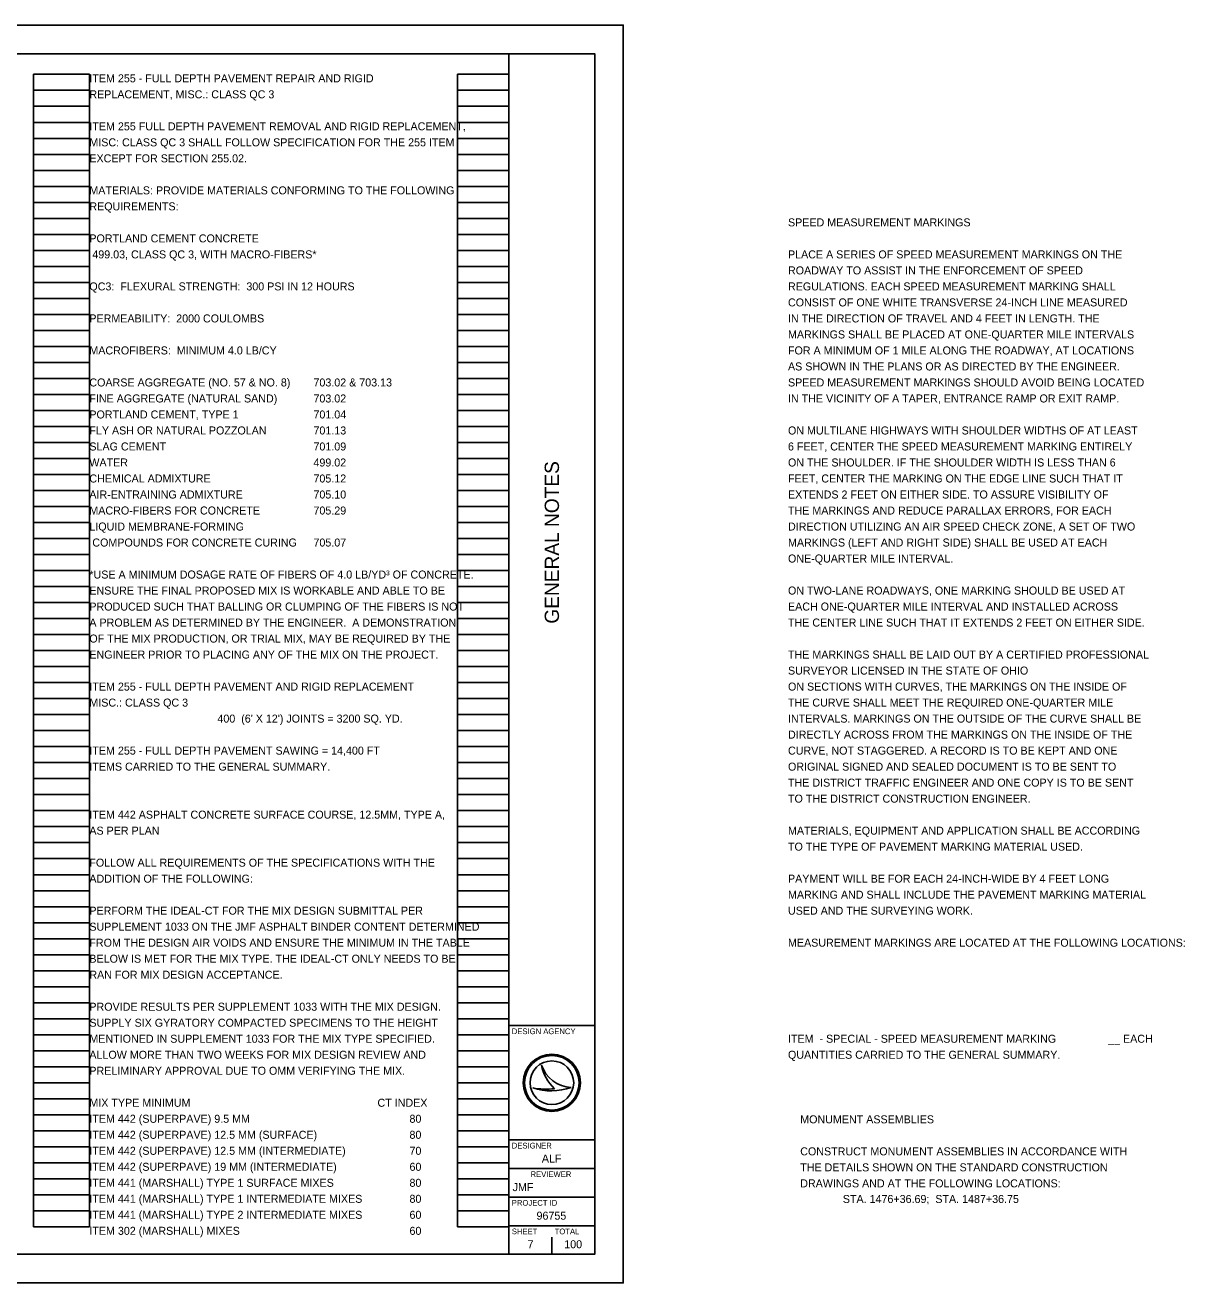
# Model space of a CAD drawing. Extents: x 0 to 43.8, y 0 to 22.
# Drawn here: x 23.54 to 43.82, y 0 to 22 of the extents above; entities that cross this region are included whole.
import ezdxf

# ---------------------------------------------------------------- set-up
doc = ezdxf.new("R2010")
doc.units = 0
for name, color, linetype in [('Default', 7, 'Continuous'), ('SH_Border', 7, 'Continuous'), ('SH_Cut_Line', 7, 'Continuous'), ('SH_Data', 7, 'Continuous'), ('SH_Text', 7, 'Continuous')]:
    doc.layers.add(name, color=color, linetype=linetype)

msp = doc.modelspace()

# ---------------------------------------------------------------- linework, layer by layer
at = {"layer": 'SH_Border'}
for p, q in [((32, 0.5), (32, 21.5)), ((32, 4.5), (33.5, 4.5)), ((32, 2.5), (33.5, 2.5)), ((32, 2), (33.5, 2)), ((32, 1.5), (33.5, 1.5)), ((32, 1), (33.5, 1))]:
    msp.add_line(p, q, dxfattribs=at)
msp.add_lwpolyline([(1.5, 21.5), (33.5, 21.5), (33.5, 0.5), (1.5, 0.5)], close=True, dxfattribs=at)
at = {"layer": 'SH_Cut_Line'}
msp.add_lwpolyline([(0, 0), (34, 0), (34, 22), (0, 22)], close=True, dxfattribs=at)
at = {"layer": 'SH_Data'}
for p, q in [((23.68, 0.98), (23.68, 21.14)), ((23.68, 21.14), (24.66, 21.14)), ((24.66, 0.98), (24.66, 21.14)), ((31.1, 0.98), (31.1, 21.14)), ((31.1, 21.14), (32, 21.14)), ((32, 0.98), (32, 21.14)), ((23.68, 20.86), (24.66, 20.86)), ((31.1, 20.86), (32, 20.86)), ((23.68, 20.58), (24.66, 20.58)), ((31.1, 20.58), (32, 20.58)), ((23.68, 20.3), (24.66, 20.3)), ((31.1, 20.3), (32, 20.3)), ((23.68, 20.02), (24.66, 20.02)), ((31.1, 20.02), (32, 20.02)), ((23.68, 19.74), (24.66, 19.74)), ((31.1, 19.74), (32, 19.74)), ((23.68, 19.46), (24.66, 19.46)), ((31.1, 19.46), (32, 19.46)), ((23.68, 19.18), (24.66, 19.18)), ((31.1, 19.18), (32, 19.18)), ((23.68, 18.9), (24.66, 18.9)), ((31.1, 18.9), (32, 18.9)), ((23.68, 18.62), (24.66, 18.62)), ((31.1, 18.62), (32, 18.62)), ((23.68, 18.34), (24.66, 18.34)), ((31.1, 18.34), (32, 18.34)), ((23.68, 18.06), (24.66, 18.06)), ((31.1, 18.06), (32, 18.06)), ((23.68, 17.78), (24.66, 17.78)), ((31.1, 17.78), (32, 17.78)), ((23.68, 17.5), (24.66, 17.5)), ((31.1, 17.5), (32, 17.5)), ((23.68, 17.22), (24.66, 17.22)), ((31.1, 17.22), (32, 17.22)), ((23.68, 16.94), (24.66, 16.94)), ((31.1, 16.94), (32, 16.94)), ((23.68, 16.66), (24.66, 16.66)), ((31.1, 16.66), (32, 16.66)), ((23.68, 16.38), (24.66, 16.38)), ((31.1, 16.38), (32, 16.38)), ((23.68, 16.1), (24.66, 16.1)), ((31.1, 16.1), (32, 16.1)), ((23.68, 15.82), (24.66, 15.82)), ((31.1, 15.82), (32, 15.82)), ((23.68, 15.54), (24.66, 15.54)), ((31.1, 15.54), (32, 15.54)), ((23.68, 15.26), (24.66, 15.26)), ((31.1, 15.26), (32, 15.26)), ((23.68, 14.98), (24.66, 14.98)), ((31.1, 14.98), (32, 14.98)), ((23.68, 14.7), (24.66, 14.7)), ((31.1, 14.7), (32, 14.7)), ((23.68, 14.42), (24.66, 14.42)), ((31.1, 14.42), (32, 14.42)), ((23.68, 14.14), (24.66, 14.14)), ((31.1, 14.14), (32, 14.14)), ((23.68, 13.86), (24.66, 13.86)), ((31.1, 13.86), (32, 13.86)), ((23.68, 13.58), (24.66, 13.58)), ((31.1, 13.58), (32, 13.58)), ((23.68, 13.3), (24.66, 13.3)), ((31.1, 13.3), (32, 13.3)), ((23.68, 13.02), (24.66, 13.02)), ((31.1, 13.02), (32, 13.02)), ((23.68, 12.74), (24.66, 12.74)), ((31.1, 12.74), (32, 12.74)), ((23.68, 12.46), (24.66, 12.46)), ((31.1, 12.46), (32, 12.46)), ((23.68, 12.18), (24.66, 12.18)), ((31.1, 12.18), (32, 12.18)), ((23.68, 11.9), (24.66, 11.9)), ((31.1, 11.9), (32, 11.9)), ((23.68, 11.62), (24.66, 11.62)), ((31.1, 11.62), (32, 11.62)), ((23.68, 11.34), (24.66, 11.34)), ((31.1, 11.34), (32, 11.34)), ((23.68, 11.06), (24.66, 11.06)), ((31.1, 11.06), (32, 11.06)), ((23.68, 10.78), (24.66, 10.78)), ((31.1, 10.78), (32, 10.78)), ((23.68, 10.5), (24.66, 10.5)), ((31.1, 10.5), (32, 10.5)), ((23.68, 10.22), (24.66, 10.22)), ((31.1, 10.22), (32, 10.22)), ((23.68, 9.94), (24.66, 9.94)), ((31.1, 9.94), (32, 9.94)), ((23.68, 9.66), (24.66, 9.66)), ((31.1, 9.66), (32, 9.66)), ((23.68, 9.38), (24.66, 9.38)), ((31.1, 9.38), (32, 9.38)), ((23.68, 9.1), (24.66, 9.1)), ((31.1, 9.1), (32, 9.1)), ((23.68, 8.82), (24.66, 8.82)), ((31.1, 8.82), (32, 8.82)), ((23.68, 8.54), (24.66, 8.54)), ((31.1, 8.54), (32, 8.54)), ((23.68, 8.26), (24.66, 8.26)), ((31.1, 8.26), (32, 8.26)), ((23.68, 7.98), (24.66, 7.98)), ((31.1, 7.98), (32, 7.98)), ((23.68, 7.7), (24.66, 7.7)), ((31.1, 7.7), (32, 7.7)), ((23.68, 7.42), (24.66, 7.42)), ((31.1, 7.42), (32, 7.42)), ((23.68, 7.14), (24.66, 7.14)), ((31.1, 7.14), (32, 7.14)), ((23.68, 6.86), (24.66, 6.86)), ((31.1, 6.86), (32, 6.86)), ((23.68, 6.58), (24.66, 6.58)), ((31.1, 6.58), (32, 6.58)), ((23.68, 6.3), (24.66, 6.3)), ((31.1, 6.3), (32, 6.3)), ((23.68, 6.02), (24.66, 6.02)), ((31.1, 6.02), (32, 6.02)), ((23.68, 5.74), (24.66, 5.74)), ((31.1, 5.74), (32, 5.74)), ((23.68, 5.46), (24.66, 5.46)), ((31.1, 5.46), (32, 5.46)), ((23.68, 5.18), (24.66, 5.18)), ((31.1, 5.18), (32, 5.18)), ((23.68, 4.9), (24.66, 4.9)), ((31.1, 4.9), (32, 4.9)), ((23.68, 4.62), (24.66, 4.62)), ((31.1, 4.62), (32, 4.62)), ((23.68, 4.34), (24.66, 4.34)), ((31.1, 4.34), (32, 4.34)), ((23.68, 4.06), (24.66, 4.06)), ((31.1, 4.06), (32, 4.06)), ((23.68, 3.78), (24.66, 3.78)), ((31.1, 3.78), (32, 3.78)), ((32.567, 3.81), (32.567, 3.81)), ((23.68, 3.5), (24.66, 3.5)), ((31.1, 3.5), (32, 3.5)), ((32.417, 3.41), (32.417, 3.41)), ((32.75, 3.5), (32.75, 3.5)), ((33.087, 3.419), (33.087, 3.419)), ((23.68, 3.22), (24.66, 3.22)), ((31.1, 3.22), (32, 3.22)), ((23.68, 2.94), (24.66, 2.94)), ((31.1, 2.94), (32, 2.94)), ((23.68, 2.66), (24.66, 2.66)), ((31.1, 2.66), (32, 2.66)), ((23.68, 2.38), (24.66, 2.38)), ((31.1, 2.38), (32, 2.38)), ((23.68, 2.1), (24.66, 2.1)), ((31.1, 2.1), (32, 2.1)), ((23.68, 1.82), (24.66, 1.82)), ((31.1, 1.82), (32, 1.82)), ((23.68, 1.54), (24.66, 1.54)), ((31.1, 1.54), (32, 1.54)), ((23.68, 1.26), (24.66, 1.26)), ((31.1, 1.26), (32, 1.26)), ((23.68, 0.98), (24.66, 0.98)), ((31.1, 0.98), (32, 0.98)), ((32.375, 0.675), (32.375, 0.675)), ((32.75, 0.5), (32.75, 0.8))]:
    msp.add_line(p, q, dxfattribs=at)
for radius in [0.5, 0.477, 0.477, 0.382]:
    msp.add_circle((32.75, 3.5), radius, dxfattribs=at)
for centre, radius, start, end in [((33.116, 3.998), 0.58, 198.9257, 198.9319), ((33.347, 3.97), 0.796, 191.6379, 191.6421), ((33.116, 3.998), 0.58, 198.9319, 267.1657), ((33.347, 3.97), 0.796, 191.6421, 226.0947), ((32.739, 4.37), 1.013, 251.4576, 290.0832), ((32.648, 4.654), 1.266, 259.4964, 259.4995), ((32.739, 4.37), 1.013, 251.4527, 251.4576), ((32.648, 4.654), 1.266, 259.4995, 276.6672)]:
    msp.add_arc(centre, radius, start, end, dxfattribs=at)

# ---------------------------------------------------------------- texts
at = {"layer": 'Default'}
for s, p in [('ITEM 442 ASPHALT CONCRETE SURFACE COURSE, 12.5MM, TYPE A,', (24.66, 8.12)), ('AS PER PLAN', (24.66, 7.84)), ('FOLLOW ALL REQUIREMENTS OF THE SPECIFICATIONS WITH THE ', (24.66, 7.28)), ('ADDITION OF THE FOLLOWING:', (24.66, 7)), ('PERFORM THE IDEAL-CT FOR THE MIX DESIGN SUBMITTAL PER', (24.66, 6.44)), ('SUPPLEMENT 1033 ON THE JMF ASPHALT BINDER CONTENT DETERMINED', (24.66, 6.16)), ('FROM THE DESIGN AIR VOIDS AND ENSURE THE MINIMUM IN THE TABLE', (24.66, 5.88)), ('BELOW IS MET FOR THE MIX TYPE. THE IDEAL-CT ONLY NEEDS TO BE', (24.66, 5.6)), ('RAN FOR MIX DESIGN ACCEPTANCE.', (24.66, 5.32)), ('PROVIDE RESULTS PER SUPPLEMENT 1033 WITH THE MIX DESIGN.', (24.66, 4.76)), ('SUPPLY SIX GYRATORY COMPACTED SPECIMENS TO THE HEIGHT', (24.66, 4.48)), ('MENTIONED IN SUPPLEMENT 1033 FOR THE MIX TYPE SPECIFIED.', (24.66, 4.2)), ('ALLOW MORE THAN TWO WEEKS FOR MIX DESIGN REVIEW AND', (24.66, 3.92)), ('PRELIMINARY APPROVAL DUE TO OMM VERIFYING THE MIX. ', (24.66, 3.64)), ('MIX TYPE MINIMUM                                           ', (24.66, 3.08)), ('CT INDEX', (29.7, 3.08)), ('ITEM 442 (SUPERPAVE) 9.5 MM                              ', (24.66, 2.8)), ('80', (30.26, 2.8)), ('ITEM 442 (SUPERPAVE) 12.5 MM (SURFACE)             ', (24.66, 2.52)), ('80', (30.26, 2.52)), ('ITEM 442 (SUPERPAVE) 12.5 MM (INTERMEDIATE)     ', (24.66, 2.24)), ('70', (30.26, 2.24)), ('ITEM 442 (SUPERPAVE) 19 MM (INTERMEDIATE)        ', (24.66, 1.96)), ('60', (30.26, 1.96)), ('ITEM 441 (MARSHALL) TYPE 1 SURFACE MIXES           ', (24.66, 1.68)), ('80', (30.26, 1.68)), ('ITEM 441 (MARSHALL) TYPE 1 INTERMEDIATE MIXES     ', (24.66, 1.4)), ('80', (30.26, 1.4)), ('ITEM 441 (MARSHALL) TYPE 2 INTERMEDIATE MIXES     ', (24.66, 1.12)), ('60', (30.26, 1.12)), ('ITEM 302 (MARSHALL) MIXES                                      ', (24.66, 0.84)), ('60', (30.26, 0.84))]:
    msp.add_text(s, height=0.14, dxfattribs=at).set_placement(p)
at = {"layer": 'SH_Data'}
msp.add_text('GENERAL NOTES', height=0.25, rotation=90, dxfattribs=at).set_placement((32.875, 11.531))
for s, height, p in [('DESIGN AGENCY', 0.1, (32.05, 4.35)), ('DESIGNER', 0.1, (32.05, 2.35)), ('ALF', 0.14, (32.575, 2.105)), ('REVIEWER', 0.1, (32.378, 1.85)), ('JMF', 0.14, (32.064, 1.605)), ('PROJECT ID', 0.1, (32.05, 1.35)), ('96755', 0.14, (32.482, 1.105)), ('SHEET', 0.1, (32.05, 0.85)), ('TOTAL', 0.1, (32.8, 0.85)), ('7', 0.14, (32.325, 0.605)), ('100', 0.14, (32.967, 0.605))]:
    msp.add_text(s, height=height, dxfattribs=at).set_placement(p)
at = {"layer": 'SH_Text'}
for s, p in [('ITEM 255 - FULL DEPTH PAVEMENT REPAIR AND RIGID', (24.66, 21)), ('REPLACEMENT, MISC.: CLASS QC 3', (24.66, 20.72)), ('ITEM 255 FULL DEPTH PAVEMENT REMOVAL AND RIGID REPLACEMENT,', (24.66, 20.16)), ('MISC: CLASS QC 3 SHALL FOLLOW SPECIFICATION FOR THE 255 ITEM', (24.66, 19.88)), ('EXCEPT FOR SECTION 255.02.', (24.66, 19.6)), ('MATERIALS: PROVIDE MATERIALS CONFORMING TO THE FOLLOWING', (24.66, 19.04)), ('REQUIREMENTS:', (24.66, 18.76)), ('SPEED MEASUREMENT MARKINGS', (36.881, 18.48)), ('PORTLAND CEMENT CONCRETE', (24.66, 18.2)), (' 499.03, CLASS QC 3, WITH MACRO-FIBERS*', (24.66, 17.92)), ('PLACE A SERIES OF SPEED MEASUREMENT MARKINGS ON THE', (36.881, 17.92)), ('ROADWAY TO ASSIST IN THE ENFORCEMENT OF SPEED', (36.881, 17.64)), ('QC3:  FLEXURAL STRENGTH:  300 PSI IN 12 HOURS', (24.66, 17.36)), ('REGULATIONS. EACH SPEED MEASUREMENT MARKING SHALL', (36.881, 17.36)), ('CONSIST OF ONE WHITE TRANSVERSE 24-INCH LINE MEASURED', (36.881, 17.08)), ('PERMEABILITY:  2000 COULOMBS', (24.66, 16.8)), ('IN THE DIRECTION OF TRAVEL AND 4 FEET IN LENGTH. THE', (36.881, 16.8)), ('MARKINGS SHALL BE PLACED AT ONE-QUARTER MILE INTERVALS', (36.881, 16.52)), ('MACROFIBERS:  MINIMUM 4.0 LB/CY', (24.66, 16.24)), ('FOR A MINIMUM OF 1 MILE ALONG THE ROADWAY, AT LOCATIONS', (36.881, 16.24)), ('AS SHOWN IN THE PLANS OR AS DIRECTED BY THE ENGINEER.', (36.881, 15.96)), ('COARSE AGGREGATE (NO. 57 & NO. 8)', (24.66, 15.68)), ('703.02 & 703.13', (28.58, 15.68)), ('SPEED MEASUREMENT MARKINGS SHOULD AVOID BEING LOCATED', (36.881, 15.68)), ('FINE AGGREGATE (NATURAL SAND)', (24.66, 15.4)), ('703.02', (28.58, 15.4)), ('IN THE VICINITY OF A TAPER, ENTRANCE RAMP OR EXIT RAMP.', (36.881, 15.4)), ('PORTLAND CEMENT, TYPE 1', (24.66, 15.12)), ('701.04', (28.58, 15.12)), ('FLY ASH OR NATURAL POZZOLAN', (24.66, 14.84)), ('701.13', (28.58, 14.84)), ('ON MULTILANE HIGHWAYS WITH SHOULDER WIDTHS OF AT LEAST', (36.881, 14.84)), ('SLAG CEMENT', (24.66, 14.56)), ('701.09', (28.58, 14.56)), ('6 FEET, CENTER THE SPEED MEASUREMENT MARKING ENTIRELY', (36.881, 14.56)), ('WATER', (24.66, 14.28)), ('499.02', (28.58, 14.28)), ('ON THE SHOULDER. IF THE SHOULDER WIDTH IS LESS THAN 6', (36.881, 14.28)), ('CHEMICAL ADMIXTURE', (24.66, 14)), ('705.12', (28.58, 14)), ('FEET, CENTER THE MARKING ON THE EDGE LINE SUCH THAT IT', (36.881, 14)), ('AIR-ENTRAINING ADMIXTURE', (24.66, 13.72)), ('705.10', (28.58, 13.72)), ('EXTENDS 2 FEET ON EITHER SIDE. TO ASSURE VISIBILITY OF', (36.881, 13.72)), ('MACRO-FIBERS FOR CONCRETE', (24.66, 13.44)), ('705.29', (28.58, 13.44)), ('THE MARKINGS AND REDUCE PARALLAX ERRORS, FOR EACH', (36.881, 13.44)), ('LIQUID MEMBRANE-FORMING', (24.66, 13.16)), ('DIRECTION UTILIZING AN AIR SPEED CHECK ZONE, A SET OF TWO', (36.881, 13.16)), (' COMPOUNDS FOR CONCRETE CURING', (24.66, 12.88)), ('705.07', (28.58, 12.88)), ('MARKINGS (LEFT AND RIGHT SIDE) SHALL BE USED AT EACH', (36.881, 12.88)), ('ONE-QUARTER MILE INTERVAL.', (36.881, 12.6)), ('*USE A MINIMUM DOSAGE RATE OF FIBERS OF 4.0 LB/YD³ OF CONCRETE.', (24.66, 12.32)), ('ENSURE THE FINAL PROPOSED MIX IS WORKABLE AND ABLE TO BE', (24.66, 12.04)), ('ON TWO-LANE ROADWAYS, ONE MARKING SHOULD BE USED AT', (36.881, 12.04)), ('PRODUCED SUCH THAT BALLING OR CLUMPING OF THE FIBERS IS NOT', (24.66, 11.76)), ('EACH ONE-QUARTER MILE INTERVAL AND INSTALLED ACROSS', (36.881, 11.76)), ('A PROBLEM AS DETERMINED BY THE ENGINEER.  A DEMONSTRATION', (24.66, 11.48)), ('THE CENTER LINE SUCH THAT IT EXTENDS 2 FEET ON EITHER SIDE.', (36.881, 11.48)), ('OF THE MIX PRODUCTION, OR TRIAL MIX, MAY BE REQUIRED BY THE', (24.66, 11.2)), ('ENGINEER PRIOR TO PLACING ANY OF THE MIX ON THE PROJECT.', (24.66, 10.92)), ('THE MARKINGS SHALL BE LAID OUT BY A CERTIFIED PROFESSIONAL', (36.881, 10.92)), ('SURVEYOR LICENSED IN THE STATE OF OHIO', (36.881, 10.64)), ('ITEM 255 - FULL DEPTH PAVEMENT AND RIGID REPLACEMENT', (24.66, 10.36)), ('ON SECTIONS WITH CURVES, THE MARKINGS ON THE INSIDE OF', (36.881, 10.36)), ('MISC.: CLASS QC 3', (24.66, 10.08)), ('THE CURVE SHALL MEET THE REQUIRED ONE-QUARTER MILE', (36.881, 10.08)), ("400  (6' X 12') JOINTS = 3200 SQ. YD.", (26.9, 9.8)), ('INTERVALS. MARKINGS ON THE OUTSIDE OF THE CURVE SHALL BE', (36.881, 9.8)), ('DIRECTLY ACROSS FROM THE MARKINGS ON THE INSIDE OF THE', (36.881, 9.52)), ('ITEM 255 - FULL DEPTH PAVEMENT SAWING = 14,400 FT', (24.66, 9.24)), ('CURVE, NOT STAGGERED. A RECORD IS TO BE KEPT AND ONE', (36.881, 9.24)), ('ITEMS CARRIED TO THE GENERAL SUMMARY.', (24.66, 8.96)), ('ORIGINAL SIGNED AND SEALED DOCUMENT IS TO BE SENT TO', (36.881, 8.96)), ('THE DISTRICT TRAFFIC ENGINEER AND ONE COPY IS TO BE SENT', (36.881, 8.68)), ('TO THE DISTRICT CONSTRUCTION ENGINEER.', (36.881, 8.4)), ('MATERIALS, EQUIPMENT AND APPLICATION SHALL BE ACCORDING', (36.881, 7.84)), ('TO THE TYPE OF PAVEMENT MARKING MATERIAL USED.', (36.881, 7.56)), ('PAYMENT WILL BE FOR EACH 24-INCH-WIDE BY 4 FEET LONG', (36.881, 7)), ('MARKING AND SHALL INCLUDE THE PAVEMENT MARKING MATERIAL', (36.881, 6.72)), ('USED AND THE SURVEYING WORK.', (36.881, 6.44)), ('MEASUREMENT MARKINGS ARE LOCATED AT THE FOLLOWING LOCATIONS:', (36.881, 5.88)), ('ITEM  - SPECIAL - SPEED MEASUREMENT MARKING', (36.881, 4.2)), ('__ EACH', (42.481, 4.2)), ('QUANTITIES CARRIED TO THE GENERAL SUMMARY.', (36.881, 3.92)), ('MONUMENT ASSEMBLIES', (37.095, 2.79)), ('CONSTRUCT MONUMENT ASSEMBLIES IN ACCORDANCE WITH', (37.095, 2.23)), ('THE DETAILS SHOWN ON THE STANDARD CONSTRUCTION', (37.095, 1.95)), ('DRAWINGS AND AT THE FOLLOWING LOCATIONS:', (37.095, 1.67)), ('STA. 1476+36.69;  STA. 1487+36.75', (37.84, 1.397))]:
    msp.add_text(s, height=0.14, dxfattribs=at).set_placement(p)

doc.saveas('drawing.dxf')
